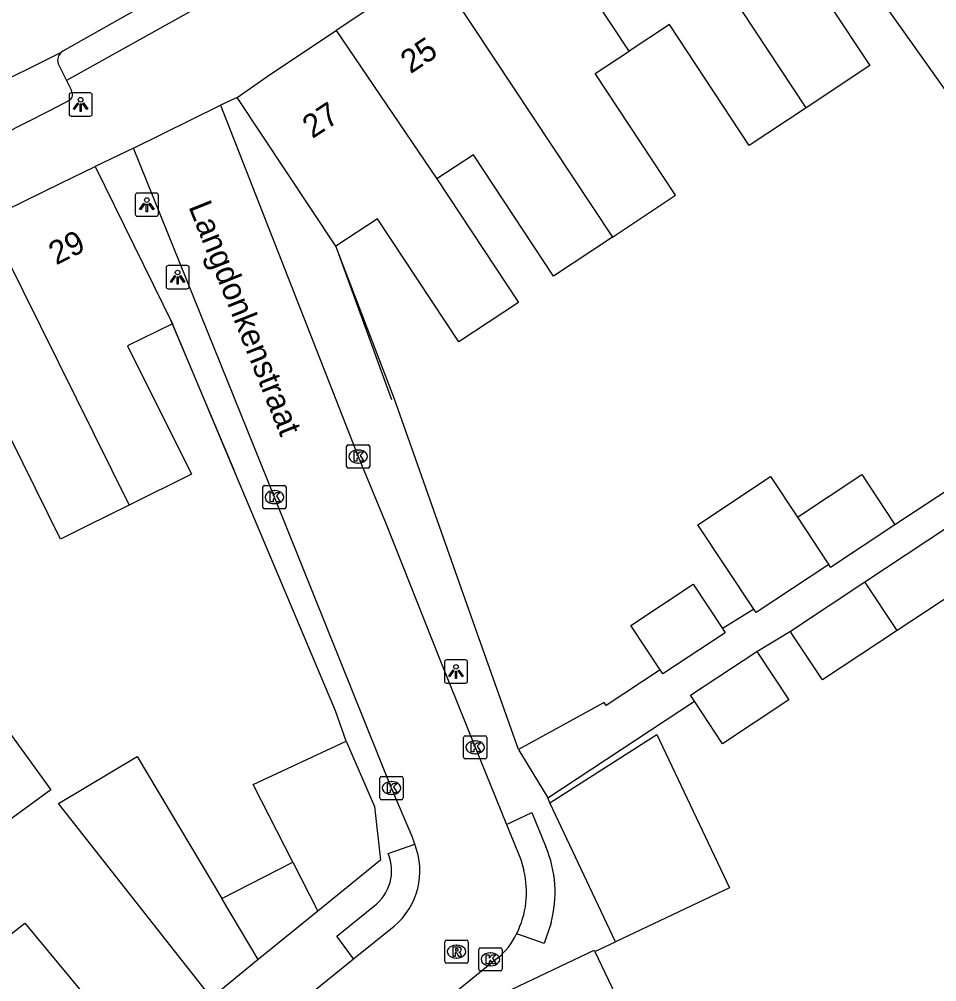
# Model space of a CAD drawing. Extents: x 159718 to 160783, y 383290 to 384030.
# Drawn here: x 160388.58 to 160428.04, y 383488.36 to 383529.73 of the extents above; entities that cross this region are included whole.
import ezdxf

# ---------------------------------------------------------------- set-up
doc = ezdxf.new("R2010")
doc.units = 0
for name, color, linetype in [('IMGEO_Kolk', 7, 'Continuous'), ('IMGEO_Lichtpunt', 7, 'Continuous'), ('IMGEO_Muur', 7, 'Continuous'), ('IMGEO_Openbare_ruimte_label', 7, 'Continuous'), ('IMGEO_Pand', 7, 'Continuous'), ('IMGEO_Pand_nummerreeks', 7, 'Continuous'), ('IMGEO_Rijbaan_lokaal_open', 7, 'Continuous'), ('IMGEO_Rioolput', 7, 'Continuous'), ('IMGEO_Voetpad_open', 7, 'Continuous')]:
    doc.layers.add(name, color=color, linetype=linetype)

msp = doc.modelspace()

# ---------------------------------------------------------------- linework, layer by layer
at = {"layer": 'IMGEO_Kolk'}
for p, q in [((160402.653, 383510.511), (160402.653, 383511.363)), ((160402.728, 383511.437), (160403.58, 383511.437)), ((160403.654, 383511.363), (160403.654, 383510.511)), ((160403.141, 383511.217), (160403.166, 383511.217)), ((160403.164, 383510.657), (160403.139, 383510.657)), ((160403.58, 383510.437), (160402.728, 383510.437)), ((160399.126, 383509.692), (160399.978, 383509.692)), ((160399.051, 383508.766), (160399.051, 383509.618)), ((160399.539, 383509.472), (160399.564, 383509.472)), ((160400.052, 383509.618), (160400.052, 383508.766)), ((160399.562, 383508.912), (160399.537, 383508.912)), ((160399.978, 383508.692), (160399.126, 383508.692)), ((160407.76, 383498.937), (160408.612, 383498.937)), ((160407.685, 383498.011), (160407.685, 383498.863)), ((160408.173, 383498.717), (160408.198, 383498.717)), ((160408.686, 383498.863), (160408.686, 383498.011)), ((160408.196, 383498.157), (160408.171, 383498.157)), ((160408.612, 383497.937), (160407.76, 383497.937)), ((160404.087, 383496.261), (160404.087, 383497.113)), ((160404.162, 383497.187), (160405.014, 383497.187)), ((160404.575, 383496.967), (160404.6, 383496.967)), ((160405.088, 383497.113), (160405.088, 383496.261)), ((160404.598, 383496.407), (160404.573, 383496.407)), ((160405.014, 383496.187), (160404.162, 383496.187)), ((160408.415, 383489.823), (160409.267, 383489.823)), ((160408.34, 383488.897), (160408.34, 383489.749)), ((160408.828, 383489.603), (160408.853, 383489.603)), ((160409.341, 383489.749), (160409.341, 383488.897)), ((160408.851, 383489.043), (160408.826, 383489.043)), ((160409.267, 383488.823), (160408.415, 383488.823))]:
    msp.add_line(p, q, dxfattribs=at)
for points in [[(160402.653, 383510.511), (160402.653, 383511.363)], [(160402.728, 383511.437), (160403.58, 383511.437)], [(160403.654, 383511.363), (160403.654, 383510.511)], [(160402.974, 383511.137), (160403.097, 383511.137), (160403.097, 383510.986), (160403.227, 383511.137), (160403.391, 383511.137), (160403.245, 383510.986), (160403.398, 383510.737), (160403.246, 383510.737), (160403.161, 383510.901), (160403.097, 383510.834), (160403.097, 383510.737), (160402.974, 383510.737), (160402.974, 383511.137)], [(160403.58, 383510.437), (160402.728, 383510.437)], [(160399.126, 383509.692), (160399.978, 383509.692)], [(160399.051, 383508.766), (160399.051, 383509.618)], [(160399.372, 383509.392), (160399.495, 383509.392), (160399.495, 383509.241), (160399.625, 383509.392), (160399.789, 383509.392), (160399.643, 383509.241), (160399.796, 383508.992), (160399.644, 383508.992), (160399.559, 383509.156), (160399.495, 383509.089), (160399.495, 383508.992), (160399.372, 383508.992), (160399.372, 383509.392)], [(160400.052, 383509.618), (160400.052, 383508.766)], [(160399.978, 383508.692), (160399.126, 383508.692)], [(160407.76, 383498.937), (160408.612, 383498.937)], [(160407.685, 383498.011), (160407.685, 383498.863)], [(160408.006, 383498.637), (160408.129, 383498.637), (160408.129, 383498.486), (160408.259, 383498.637), (160408.423, 383498.637), (160408.277, 383498.486), (160408.43, 383498.237), (160408.278, 383498.237), (160408.193, 383498.401), (160408.129, 383498.334), (160408.129, 383498.237), (160408.006, 383498.237), (160408.006, 383498.637)], [(160408.686, 383498.863), (160408.686, 383498.011)], [(160408.612, 383497.937), (160407.76, 383497.937)], [(160404.087, 383496.261), (160404.087, 383497.113)], [(160404.162, 383497.187), (160405.014, 383497.187)], [(160404.408, 383496.887), (160404.531, 383496.887), (160404.531, 383496.736), (160404.661, 383496.887), (160404.825, 383496.887), (160404.679, 383496.736), (160404.832, 383496.487), (160404.68, 383496.487), (160404.595, 383496.651), (160404.531, 383496.584), (160404.531, 383496.487), (160404.408, 383496.487), (160404.408, 383496.887)], [(160405.088, 383497.113), (160405.088, 383496.261)], [(160405.014, 383496.187), (160404.162, 383496.187)], [(160408.415, 383489.823), (160409.267, 383489.823)], [(160408.34, 383488.897), (160408.34, 383489.749)], [(160408.661, 383489.523), (160408.784, 383489.523), (160408.784, 383489.372), (160408.914, 383489.523), (160409.078, 383489.523), (160408.932, 383489.372), (160409.085, 383489.123), (160408.933, 383489.123), (160408.848, 383489.287), (160408.784, 383489.22), (160408.784, 383489.123), (160408.661, 383489.123), (160408.661, 383489.523)], [(160409.341, 383489.749), (160409.341, 383488.897)], [(160409.267, 383488.823), (160408.415, 383488.823)]]:
    msp.add_lwpolyline(points, dxfattribs=at)
for centre, start, end in [((160402.73, 383511.361), 91.552, 178.448), ((160402.73, 383511.361), 91.552, 178.448), ((160403.578, 383511.361), 1.552, 88.448), ((160403.578, 383511.361), 1.552, 88.448), ((160402.73, 383510.513), 181.552, 268.448), ((160402.73, 383510.513), 181.552, 268.448), ((160403.578, 383510.513), 271.552, 358.448), ((160403.578, 383510.513), 271.552, 358.448), ((160399.128, 383509.616), 91.552, 178.448), ((160399.128, 383509.616), 91.552, 178.448), ((160399.976, 383509.616), 1.552, 88.448), ((160399.976, 383509.616), 1.552, 88.448), ((160399.128, 383508.768), 181.552, 268.448), ((160399.128, 383508.768), 181.552, 268.448), ((160399.976, 383508.768), 271.552, 358.448), ((160399.976, 383508.768), 271.552, 358.448), ((160407.762, 383498.861), 91.552, 178.448), ((160407.762, 383498.861), 91.552, 178.448), ((160408.61, 383498.861), 1.552, 88.448), ((160408.61, 383498.861), 1.552, 88.448), ((160407.762, 383498.013), 181.552, 268.448), ((160407.762, 383498.013), 181.552, 268.448), ((160408.61, 383498.013), 271.552, 358.448), ((160408.61, 383498.013), 271.552, 358.448), ((160404.164, 383497.111), 91.552, 178.448), ((160404.164, 383497.111), 91.552, 178.448), ((160405.012, 383497.111), 1.552, 88.448), ((160405.012, 383497.111), 1.552, 88.448), ((160404.164, 383496.263), 181.552, 268.448), ((160404.164, 383496.263), 181.552, 268.448), ((160405.012, 383496.263), 271.552, 358.448), ((160405.012, 383496.263), 271.552, 358.448), ((160408.417, 383489.747), 91.552, 178.448), ((160408.417, 383489.747), 91.552, 178.448), ((160409.265, 383489.747), 1.552, 88.448), ((160409.265, 383489.747), 1.552, 88.448), ((160408.417, 383488.899), 181.552, 268.448), ((160408.417, 383488.899), 181.552, 268.448), ((160409.265, 383488.899), 271.552, 358.448), ((160409.265, 383488.899), 271.552, 358.448)]:
    msp.add_arc(centre, 0.0765, start, end, dxfattribs=at)
for centre, major_axis, ratio, start_param, end_param in [((160403.14, 383510.937), (-0.387, 0.002), 0.722429, 4.712389, 7.853982), ((160403.165, 383510.937), (-0.39, 0.002), 0.717154, 1.570796, 4.712389), ((160399.538, 383509.192), (-0.387, 0.002), 0.722429, 4.712389, 7.853982), ((160399.563, 383509.192), (-0.39, 0.002), 0.717154, 1.570796, 4.712389), ((160408.172, 383498.437), (-0.387, 0.002), 0.722429, 4.712389, 7.853982), ((160408.197, 383498.437), (-0.39, 0.002), 0.717154, 1.570796, 4.712389), ((160404.574, 383496.687), (-0.387, 0.002), 0.722429, 4.712389, 7.853982), ((160404.599, 383496.687), (-0.39, 0.002), 0.717154, 1.570796, 4.712389), ((160408.827, 383489.323), (-0.387, 0.002), 0.722429, 4.712389, 7.853982), ((160408.852, 383489.323), (-0.39, 0.002), 0.717154, 1.570796, 4.712389)]:
    msp.add_ellipse(centre, major_axis=major_axis, ratio=ratio, start_param=start_param, end_param=end_param, dxfattribs=at)
at = {"layer": 'IMGEO_Lichtpunt'}
for p, q in [((160390.718, 383526.476), (160390.718, 383525.669)), ((160390.718, 383526.476), (160390.718, 383525.669)), ((160391.62, 383526.571), (160390.812, 383526.571)), ((160391.62, 383526.571), (160390.812, 383526.571)), ((160391.714, 383525.669), (160391.714, 383526.476)), ((160391.714, 383525.669), (160391.714, 383526.476)), ((160390.812, 383525.575), (160391.62, 383525.575)), ((160390.812, 383525.575), (160391.62, 383525.575)), ((160393.564, 383522.166), (160393.564, 383521.359)), ((160393.564, 383522.166), (160393.564, 383521.359)), ((160394.466, 383522.261), (160393.658, 383522.261)), ((160394.466, 383522.261), (160393.658, 383522.261)), ((160394.56, 383521.359), (160394.56, 383522.166)), ((160394.56, 383521.359), (160394.56, 383522.166)), ((160393.658, 383521.265), (160394.466, 383521.265)), ((160393.658, 383521.265), (160394.466, 383521.265)), ((160394.89, 383519.05), (160394.89, 383518.243)), ((160394.89, 383519.05), (160394.89, 383518.243)), ((160395.792, 383519.145), (160394.984, 383519.145)), ((160395.792, 383519.145), (160394.984, 383519.145)), ((160395.886, 383518.243), (160395.886, 383519.05)), ((160395.886, 383518.243), (160395.886, 383519.05)), ((160394.984, 383518.149), (160395.792, 383518.149)), ((160394.984, 383518.149), (160395.792, 383518.149)), ((160407.763, 383502.193), (160406.955, 383502.193)), ((160407.763, 383502.193), (160406.955, 383502.193)), ((160406.861, 383502.098), (160406.861, 383501.291)), ((160406.861, 383502.098), (160406.861, 383501.291)), ((160407.857, 383501.291), (160407.857, 383502.098)), ((160407.857, 383501.291), (160407.857, 383502.098)), ((160406.955, 383501.197), (160407.763, 383501.197)), ((160406.955, 383501.197), (160407.763, 383501.197))]:
    msp.add_line(p, q, dxfattribs=at)
for points in [[(160391.092, 383526.14), (160391.131, 383526.112), (160390.943, 383525.85), (160390.905, 383525.877), (160391.092, 383526.14)], [(160391.194, 383526.092), (160391.241, 383526.092), (160391.241, 383525.77), (160391.194, 383525.77), (160391.194, 383526.092)], [(160391.304, 383526.112), (160391.342, 383526.139), (160391.529, 383525.877), (160391.49, 383525.849), (160391.304, 383526.112)], [(160393.938, 383521.83), (160393.977, 383521.802), (160393.789, 383521.54), (160393.751, 383521.567), (160393.938, 383521.83)], [(160394.04, 383521.782), (160394.087, 383521.782), (160394.087, 383521.46), (160394.04, 383521.46), (160394.04, 383521.782)], [(160394.15, 383521.802), (160394.188, 383521.829), (160394.375, 383521.567), (160394.336, 383521.539), (160394.15, 383521.802)], [(160395.264, 383518.714), (160395.303, 383518.686), (160395.115, 383518.424), (160395.077, 383518.451), (160395.264, 383518.714)], [(160395.366, 383518.666), (160395.413, 383518.666), (160395.413, 383518.344), (160395.366, 383518.344), (160395.366, 383518.666)], [(160395.476, 383518.686), (160395.514, 383518.713), (160395.701, 383518.451), (160395.662, 383518.423), (160395.476, 383518.686)], [(160407.235, 383501.762), (160407.274, 383501.734), (160407.086, 383501.472), (160407.048, 383501.499), (160407.235, 383501.762)], [(160407.337, 383501.714), (160407.384, 383501.714), (160407.384, 383501.392), (160407.337, 383501.392), (160407.337, 383501.714)], [(160407.447, 383501.734), (160407.485, 383501.761), (160407.672, 383501.499), (160407.633, 383501.471), (160407.447, 383501.734)]]:
    msp.add_lwpolyline(points, dxfattribs=at)
for centre in [(160391.217, 383526.274), (160394.063, 383521.964), (160395.389, 383518.848), (160407.36, 383501.896)]:
    msp.add_circle(centre, 0.0994, dxfattribs=at)
for centre, start, end in [((160390.812, 383526.476), 90, 180), ((160390.812, 383526.476), 90, 180), ((160391.62, 383526.476), 0, 90), ((160391.62, 383526.476), 0, 90), ((160390.812, 383525.669), 180, 270), ((160390.812, 383525.669), 180, 270), ((160391.62, 383525.669), 270, 0), ((160391.62, 383525.669), 270, 360), ((160393.658, 383522.166), 90, 180), ((160393.658, 383522.166), 90, 180), ((160394.466, 383522.166), 0, 90), ((160394.466, 383522.166), 0, 90), ((160393.658, 383521.359), 180, 270), ((160393.658, 383521.359), 180, 270), ((160394.466, 383521.359), 270, 0), ((160394.466, 383521.359), 270, 360), ((160394.984, 383519.05), 90, 180), ((160394.984, 383519.05), 90, 180), ((160395.792, 383519.05), 0, 90), ((160395.792, 383519.05), 0, 90), ((160394.984, 383518.243), 180, 270), ((160394.984, 383518.243), 180, 270), ((160395.792, 383518.243), 270, 0), ((160395.792, 383518.243), 270, 360), ((160406.955, 383502.098), 90, 180), ((160406.955, 383502.098), 90, 180), ((160407.763, 383502.098), 0, 90), ((160407.763, 383502.098), 0, 90), ((160406.955, 383501.291), 180, 270), ((160406.955, 383501.291), 180, 270), ((160407.763, 383501.291), 270, 0), ((160407.763, 383501.291), 270, 360)]:
    msp.add_arc(centre, 0.0946, start, end, dxfattribs=at)
at = {"layer": 'IMGEO_Muur'}
for points in [[(160402.193, 383519.971), (160404.583, 383513.392)], [(160395.078, 383516.816), (160397.801, 383510.368)]]:
    msp.add_lwpolyline(points, dxfattribs=at)
at = {"layer": 'IMGEO_Pand'}
for points in [[(160422.422, 383525.934), (160414.703, 383537.602)], [(160414.808, 383528.361), (160410.536, 383534.819)], [(160423.195, 383534.022), (160421.684, 383532.982), (160425.151, 383527.74), (160422.422, 383525.934)], [(160406.369, 383532.036), (160402.202, 383529.253)], [(160406.369, 383532.036), (160414.087, 383520.371)], [(160422.422, 383525.934), (160419.974, 383524.315), (160416.54, 383529.507), (160414.808, 383528.361)], [(160397.943, 383526.376), (160399.386, 383527.373), (160402.202, 383529.253)], [(160402.202, 383529.253), (160406.534, 383522.868)], [(160414.087, 383520.371), (160416.806, 383522.169), (160413.348, 383527.396), (160414.808, 383528.361)], [(160402.186, 383519.987), (160397.943, 383526.376)], [(160414.087, 383520.371), (160411.556, 383518.697), (160408.108, 383523.909), (160406.534, 383522.868)], [(160387.194, 383521.134), (160390.362, 383522.691), (160391.846, 383523.398)], [(160391.846, 383523.398), (160395.165, 383516.647)], [(160406.534, 383522.868), (160410.043, 383517.564), (160407.486, 383515.871), (160403.987, 383521.158), (160402.186, 383519.987)], [(160387.194, 383521.134), (160393.304, 383508.853)], [(160395.165, 383516.647), (160393.234, 383515.698), (160395.978, 383510.183), (160393.304, 383508.853)], [(160393.304, 383508.853), (160391.502, 383507.956), (160390.358, 383507.387), (160387.658, 383512.814), (160386.118, 383512.048)], [(160420.163, 383504.383), (160417.766, 383508.006), (160420.889, 383510.072), (160422.04, 383508.332)], [(160422.04, 383508.332), (160424.811, 383510.165), (160426.163, 383508.121), (160426.24, 383508.005)], [(160422.04, 383508.332), (160423.342, 383506.364), (160423.389, 383506.292)], [(160426.24, 383508.005), (160423.469, 383506.171), (160423.389, 383506.292)], [(160424.947, 383505.546), (160428.546, 383507.927), (160429.93, 383505.834), (160429.533, 383505.571)], [(160423.389, 383506.292), (160420.266, 383504.227), (160420.163, 383504.383)], [(160421.739, 383503.424), (160424.947, 383505.546)], [(160426.331, 383503.454), (160424.947, 383505.546)], [(160429.533, 383505.571), (160426.331, 383503.454)], [(160416.145, 383501.77), (160414.883, 383503.676), (160417.563, 383505.448), (160418.824, 383503.542)], [(160418.824, 383503.542), (160418.941, 383503.365), (160416.262, 383501.593), (160416.145, 383501.77)], [(160426.331, 383503.454), (160423.122, 383501.332), (160421.778, 383503.365), (160421.739, 383503.424)], [(160417.613, 383500.427), (160417.448, 383500.677), (160420.299, 383502.563)], [(160420.299, 383502.563), (160421.679, 383500.478), (160418.827, 383498.592), (160417.613, 383500.427)], [(160388.171, 383499.042), (160389.935, 383496.607), (160387.21, 383494.633), (160385.446, 383497.068), (160388.171, 383499.042)], [(160411.39, 383496.045), (160415.995, 383498.988), (160419.12, 383492.397), (160414.221, 383490.074)], [(160400.342, 383493.503), (160398.638, 383496.837), (160402.643, 383498.705)], [(160402.643, 383498.705), (160403.86, 383495.896), (160404.111, 383493.593), (160401.418, 383491.398)], [(160396.838, 383487.664), (160390.261, 383496.017), (160393.642, 383498.038), (160397.285, 383491.945)], [(160414.221, 383490.074), (160411.39, 383496.045)], [(160380.768, 383492.512), (160383.101, 383494.439), (160387.126, 383489.566), (160388.812, 383490.875), (160393.617, 383485.095)], [(160397.285, 383491.945), (160400.342, 383493.503)], [(160400.342, 383493.503), (160401.418, 383491.398)], [(160398.859, 383489.312), (160397.285, 383491.945)], [(160401.418, 383491.398), (160398.859, 383489.312)], [(160409.479, 383487.897), (160413.304, 383489.711), (160413.329, 383489.658)], [(160413.329, 383489.658), (160414.343, 383487.52), (160410.518, 383485.706)], [(160398.859, 383489.312), (160396.838, 383487.664)]]:
    msp.add_lwpolyline(points, dxfattribs=at)
at = {"layer": 'IMGEO_Rijbaan_lokaal_open'}
for points in [[(160396.549, 383531.817), (160390.458, 383528.368), (160390.396, 383528.326)], [(160351.034, 383509.743), (160373.389, 383519.87), (160390.396, 383528.326)], [(160393.494, 383524.2), (160397.232, 383526.042)], [(160397.232, 383526.042), (160403.154, 383510.937), (160404.358, 383508.036), (160406.668, 383502.214), (160408.186, 383498.437), (160409.53, 383495.119)], [(160405.585, 383494.274), (160405.47, 383494.609), (160404.588, 383496.687), (160399.552, 383509.192), (160393.494, 383524.2)], [(160409.53, 383495.119), (160410.143, 383493.609), (160410.279, 383493.141)], [(160402.953, 383489.352), (160404.7, 383490.752)], [(160409.144, 383489.368), (160402.03, 383483.606), (160398.126, 383480.458)], [(160395.722, 383483.5), (160399.781, 383486.775), (160402.953, 383489.352)]]:
    msp.add_lwpolyline(points, dxfattribs=at)
for centre, radius, start, end in [((160216.107, 383851.258), 354.275, 294.61833, 299.17415), ((160402.707, 383493.125), 3.099, 310.0313, 21.7585), ((160406.428, 383492.205), 3.963, 333.3144, 13.6627), ((160407.19, 383491.744), 3.076, 309.4392, 334.6159)]:
    msp.add_arc(centre, radius, start, end, dxfattribs=at)
at = {"layer": 'IMGEO_Rioolput'}
for p, q in [((160406.883, 383489.227), (160406.883, 383490.079)), ((160406.958, 383490.153), (160407.81, 383490.153)), ((160407.371, 383489.933), (160407.396, 383489.933)), ((160407.884, 383490.079), (160407.884, 383489.227)), ((160407.394, 383489.373), (160407.369, 383489.373)), ((160407.81, 383489.153), (160406.958, 383489.153))]:
    msp.add_line(p, q, dxfattribs=at)
for points in [[(160406.883, 383489.227), (160406.883, 383490.079)], [(160406.958, 383490.153), (160407.81, 383490.153)], [(160407.472, 383489.851), (160407.22, 383489.853), (160407.22, 383489.453)], [(160407.398, 383489.772), (160407.344, 383489.772), (160407.344, 383489.691)], [(160407.884, 383490.079), (160407.884, 383489.227)], [(160407.22, 383489.453), (160407.344, 383489.453), (160407.344, 383489.615), (160407.355, 383489.615)], [(160407.344, 383489.691), (160407.396, 383489.691)], [(160407.402, 383489.586), (160407.473, 383489.453), (160407.613, 383489.453), (160407.548, 383489.579)], [(160407.81, 383489.153), (160406.958, 383489.153)]]:
    msp.add_lwpolyline(points, dxfattribs=at)
for centre, radius, start, end in [((160406.96, 383490.077), 0.0765, 91.552, 178.448), ((160406.96, 383490.077), 0.0765, 91.552, 178.448), ((160407.404, 383489.676), 0.0964, 77.0061, 93.1865), ((160407.471, 383489.741), 0.109, 350.3612, 89.416), ((160407.808, 383490.077), 0.0765, 1.552, 88.448), ((160407.808, 383490.077), 0.0765, 1.552, 88.448), ((160407.354, 383489.562), 0.0533, 26.0293, 88.6989), ((160407.38, 383489.88), 0.19, 274.7715, 282.9687), ((160407.418, 383489.733), 0.0378, 276.6634, 79.6772), ((160407.469, 383489.741), 0.112, 277.5842, 350.9817), ((160407.453, 383489.526), 0.108, 29.5134, 73.7905), ((160406.96, 383489.229), 0.0765, 181.552, 268.448), ((160406.96, 383489.229), 0.0765, 181.552, 268.448), ((160407.808, 383489.229), 0.0765, 271.552, 358.448), ((160407.808, 383489.229), 0.0765, 271.552, 358.448)]:
    msp.add_arc(centre, radius, start, end, dxfattribs=at)
for centre, major_axis, ratio, start_param, end_param in [((160407.37, 383489.653), (-0.387, 0.002), 0.722429, 4.712389, 7.853982), ((160407.395, 383489.653), (-0.39, 0.002), 0.717154, 1.570796, 4.712389)]:
    msp.add_ellipse(centre, major_axis=major_axis, ratio=ratio, start_param=start_param, end_param=end_param, dxfattribs=at)
at = {"layer": 'IMGEO_Voetpad_open'}
for points in [[(160423.195, 383534.022), (160436.792, 383514.858), (160435.854, 383514.343)], [(160396.549, 383531.817), (160397.15, 383530.763), (160390.613, 383527.099)], [(160390.256, 383527.818), (160390.613, 383527.099)], [(160390.613, 383527.099), (160390.82, 383526.666)], [(160390.751, 383526.253), (160389.872, 383525.805), (160374.689, 383518.101), (160338.74, 383501.971), (160325.094, 383496.144)], [(160397.943, 383526.376), (160397.232, 383526.042)], [(160393.494, 383524.2), (160391.846, 383523.398)], [(160410.053, 383498.348), (160408.271, 383503.35), (160404.708, 383513.452), (160402.186, 383519.987)], [(160402.643, 383498.705), (160402.177, 383500), (160397.801, 383510.368), (160395.165, 383516.647)], [(160429.356, 383510.045), (160426.24, 383508.005)], [(160420.163, 383504.383), (160419.035, 383503.681), (160418.824, 383503.542)], [(160420.299, 383502.563), (160421.739, 383503.424)], [(160416.145, 383501.77), (160413.822, 383500.233), (160413.731, 383500.37), (160410.053, 383498.348)], [(160411.306, 383496.264), (160417.613, 383500.427)], [(160410.053, 383498.348), (160410.066, 383498.312), (160411.306, 383496.264)], [(160411.39, 383496.045), (160411.306, 383496.264)], [(160409.53, 383495.119), (160410.621, 383495.634), (160411.227, 383494.157)], [(160404.437, 383493.872), (160405.585, 383494.274)], [(160402.953, 383489.352), (160402.233, 383490.318), (160403.814, 383491.599)], [(160411.446, 383490.896), (160411.15, 383489.998), (160410.305, 383490.298), (160409.969, 383490.425)], [(160413.329, 383489.658), (160414.221, 383490.074)]]:
    msp.add_lwpolyline(points, dxfattribs=at)
for centre, radius, start, end in [((160390.679, 383527.975), 0.451, 128.8243, 200.3603), ((160390.55, 383526.499), 0.317, 309.2355, 31.7948), ((160406.6, 383492.208), 5.021, 344.8466, 22.8375), ((160402.701, 383493.126), 1.889, 306.0863, 23.2585)]:
    msp.add_arc(centre, radius, start, end, dxfattribs=at)

# ---------------------------------------------------------------- texts
at = {"layer": 'IMGEO_Openbare_ruimte_label'}
msp.add_text('Langdonkenstraat', height=1, rotation=291.844, dxfattribs=at).set_placement((160395.844, 383521.683))
at = {"layer": 'IMGEO_Pand_nummerreeks'}
for s, rotation, p in [('25', 33.4837, (160405.405, 383527.37)), ('27', 33.4837, (160401.185, 383524.58)), ('29', 26.4477, (160390.165, 383519.153))]:
    msp.add_text(s, height=1, rotation=rotation, dxfattribs=at).set_placement(p)

doc.saveas('drawing.dxf')
